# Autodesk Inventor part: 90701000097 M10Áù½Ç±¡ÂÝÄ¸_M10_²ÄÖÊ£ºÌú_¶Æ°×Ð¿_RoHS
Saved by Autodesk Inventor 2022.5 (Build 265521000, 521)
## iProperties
Created: 2024-07
Part Number: 90701000097 M10Áù½Ç±¡ÂÝÄ¸_M10_²ÄÖÊ£ºÌú_¶Æ°×Ð¿_RoHS
Material: Generic
Document SubType Name: Modeling
Designer: AdminForWorker
Density: 1 g/cm^3
Appearance: Default
Title: 90701000097 M10Áù½Ç±¡ÂÝÄ¸_M10_²ÄÖÊ£ºÌú_¶Æ°×Ð¿_RoHS
Author: AdminForWorker
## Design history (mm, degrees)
feature "Body1"
feature "Composite1"
body "Solid1"
body "Srf1"
